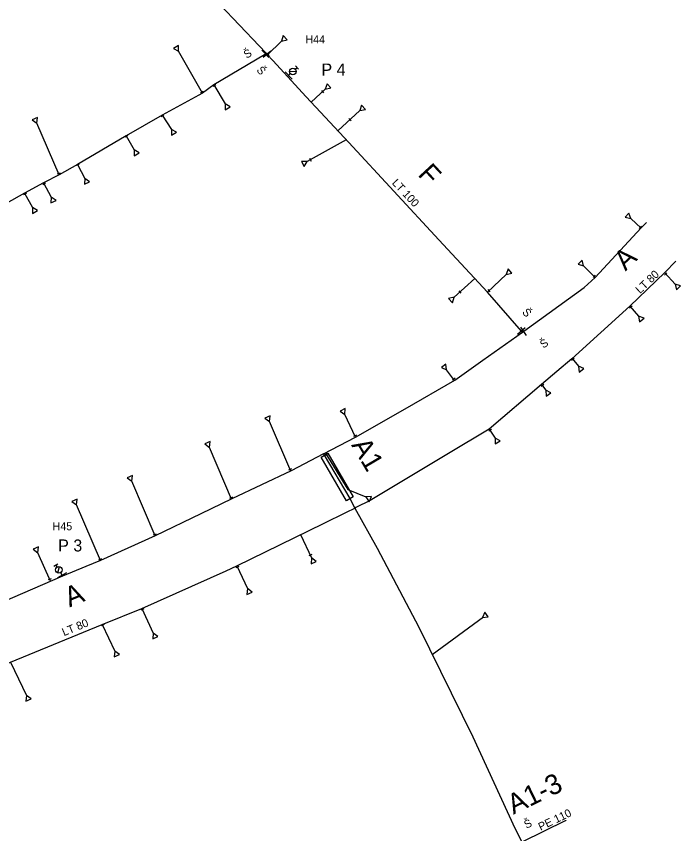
# Model space of a CAD drawing. Extents: x -574467 to -573664, y -1191210 to -1190404.
# Drawn here: x -573951.8 to -573785.7, y -1190810.5 to -1190606.2 of the extents above; entities that cross this region are included whole.
import ezdxf

# ---------------------------------------------------------------- set-up
doc = ezdxf.new("R2010")
doc.units = 0
for name, color, linetype in [('Vrstva 1', 7, 'Continuous'), ('Vrstva 12', 7, 'Continuous'), ('Vrstva 15', 7, 'Continuous'), ('Vrstva 19', 7, 'Continuous'), ('Vrstva 25', 7, 'Continuous'), ('Vrstva 28', 7, 'Continuous'), ('Vrstva 29', 7, 'Continuous'), ('Vrstva 35', 7, 'Continuous'), ('Vrstva 37', 7, 'Continuous')]:
    doc.layers.add(name, color=color, linetype=linetype)

# ---------------------------------------------------------------- blocks, each defined once
blk = doc.blocks.new('160')
at = {"layer": 'Vrstva 1'}
blk.add_circle((0, 0), 0.0458, dxfattribs=at)
blk = doc.blocks.new('147')
at = {"layer": 'Vrstva 1'}
blk.add_line((0, 1.27), (0, -1.27), dxfattribs=at)
blk = doc.blocks.new('133')
at = {"layer": 'Vrstva 1'}
for p, q in [((0.28, 0), (0, 0)), ((0.54, 0.58), (1.7, -0.58)), ((1.94, 0), (2.52, 0)), ((2.52, 0.58), (2.52, -0.58))]:
    blk.add_line(p, q, dxfattribs=at)
blk.add_circle((1.105, 0.003), 0.825, dxfattribs=at)
blk = doc.blocks.new('150')
at = {"layer": 'Vrstva 1'}
blk.add_line((0, 1.27), (0, -1.27), dxfattribs=at)
blk = doc.blocks.new('151')
at = {"layer": 'Vrstva 1'}
blk.add_line((0, 0.4), (0, -0.4), dxfattribs=at)
blk = doc.blocks.new('130')
at = {"layer": 'Vrstva 1'}
for p, q in [((1.25, 0.72), (0, 0)), ((0, 0), (1.25, -0.72)), ((1.25, -0.72), (1.25, 0.72))]:
    blk.add_line(p, q, dxfattribs=at)

msp = doc.modelspace()

# ---------------------------------------------------------------- linework, layer by layer
at = {"layer": 'Vrstva 12'}
for p, q in [((-573889.001, -1190615.839), (-573885.481, -1190612.402)), ((-573905.304, -1190625.432), (-573911.269, -1190614.947)), ((-573902.41, -1190623.348), (-573899.602, -1190628.106)), ((-573878.054, -1190627.677), (-573874.547, -1190624.423)), ((-573871.404, -1190634.844), (-573865.946, -1190629.781)), ((-573915.337, -1190630.924), (-573913.054, -1190634.482)), ((-573941.099, -1190645.798), (-573946.712, -1190632.937)), ((-573924.331, -1190636.089), (-573922.32, -1190639.608)), ((-573869.371, -1190637.036), (-573879.087, -1190642.481)), ((-573936.547, -1190643.211), (-573934.714, -1190646.744)), ((-573945.006, -1190647.851), (-573943.091, -1190651.412)), ((-573949.754, -1190650.437), (-573947.764, -1190654.011)), ((-573795.544, -1190659.125), (-573798.155, -1190656.747)), ((-573807.066, -1190671.468), (-573809.948, -1190668.542)), ((-573834.013, -1190675.152), (-573829.281, -1190670.73)), ((-573789.674, -1190670.297), (-573787.053, -1190673.13)), ((-573837.193, -1190671.724), (-573842.332, -1190676.436)), ((-573798.377, -1190678.633), (-573796.196, -1190681.141)), ((-573812.827, -1190691.761), (-573811.259, -1190693.679)), ((-573842.212, -1190697.206), (-573844.206, -1190694.537)), ((-573820.465, -1190698.209), (-573819.419, -1190699.669)), ((-573866.99, -1190711.399), (-573869.674, -1190705.688)), ((-573883.189, -1190719.88), (-573888.501, -1190707.489)), ((-573833.566, -1190709.355), (-573832.098, -1190711.627)), ((-573898.014, -1190726.854), (-573903.55, -1190713.941)), ((-573917.098, -1190736.064), (-573922.947, -1190722.391)), ((-573930.814, -1190742.242), (-573936.783, -1190728.317)), ((-573880.722, -1190735.76), (-573877.966, -1190741.585)), ((-573943.243, -1190747.418), (-573946.449, -1190740.269)), ((-573896.692, -1190743.581), (-573894.014, -1190749.253)), ((-573920.45, -1190754.23), (-573917.568, -1190760.352)), ((-573847.796, -1190765.753), (-573835.004, -1190756.299)), ((-573930.346, -1190758.182), (-573927.19, -1190764.882)), ((-573953.245, -1190767.614), (-573949.317, -1190775.972))]:
    msp.add_line(p, q, dxfattribs=at)
msp.add_lwpolyline([(-573874.542, -1190715.356), (-573868.887, -1190724.436), (-573864.43, -1190726.32)], dxfattribs=at)
at = {"layer": 'Vrstva 15'}
for p, q in [((-573889.37, -1190615.41), (-573889.54, -1190615.58)), ((-573889.12, -1190615.71), (-573889.37, -1190615.41)), ((-573825.266, -1190685.17), (-573825.51, -1190684.89)), ((-573825.19, -1190812.42), (-573814.47, -1190807.24))]:
    msp.add_line(p, q, dxfattribs=at)
for points in [[(-573889.37, -1190615.41), (-573891.12, -1190613.563), (-573900.955, -1190603.227), (-573909.109, -1190593.884), (-573929.133, -1190571.977), (-573951.697, -1190547.293)], [(-573889.54, -1190615.58), (-573889.752, -1190615.792), (-573902.4, -1190623.34), (-573905.3, -1190625.43), (-573915.33, -1190630.92), (-573924.353, -1190636.102), (-573936.554, -1190643.215), (-573941.075, -1190645.786), (-573944.998, -1190647.847), (-573949.751, -1190650.435), (-573960.986, -1190656.653)], [(-573825.51, -1190684.89), (-573834.023, -1190675.141), (-573846.16, -1190662.057), (-573868.703, -1190637.756), (-573879.333, -1190626.298), (-573887.691, -1190617.287), (-573889.12, -1190615.71)], [(-573786.877, -1190667.404), (-573789.641, -1190670.265), (-573798.387, -1190678.642), (-573812.87, -1190691.8), (-573816.661, -1190695), (-573820.453, -1190698.199), (-573833.612, -1190709.394), (-573843.764, -1190715.49), (-573863.366, -1190727.261), (-573866.886, -1190728.985), (-573867.128, -1190729.122)], [(-573867.128, -1190729.122), (-573868.368, -1190726.761), (-573874.76, -1190715.93), (-573874.965, -1190715.577)], [(-574033.223, -1190787.025), (-574029.297, -1190794.83), (-574026.879, -1190799.637), (-574026.708, -1190799.715), (-574024.277, -1190798.619), (-574015.622, -1190794.716), (-573994.702, -1190785.283), (-573967.518, -1190773.645), (-573957.376, -1190769.359), (-573953.26, -1190767.62), (-573930.346, -1190758.182), (-573920.45, -1190754.23), (-573899.351, -1190744.773), (-573896.692, -1190743.581), (-573874.974, -1190732.946), (-573869.235, -1190730.135), (-573867.128, -1190729.122)], [(-573867.128, -1190729.122), (-573861.589, -1190739.127), (-573851.202, -1190758.85), (-573837.67, -1190786.28), (-573827.129, -1190809.15), (-573825.422, -1190812.532)]]:
    msp.add_lwpolyline(points, dxfattribs=at)
at = {"layer": 'Vrstva 19'}
msp.add_line((-573825.266, -1190685.17), (-573824.942, -1190684.936), dxfattribs=at)
for points in [[(-573824.942, -1190684.936), (-573809.852, -1190674.025), (-573807.074, -1190671.476), (-573795.522, -1190659.102), (-573794.232, -1190657.731)], [(-573874.965, -1190715.577), (-573866.993, -1190711.401), (-573854.582, -1190704.292), (-573842.172, -1190697.183), (-573835.117, -1190692.17), (-573825.266, -1190685.17)], [(-573874.965, -1190715.577), (-573883.096, -1190719.837), (-573897.92, -1190726.808), (-573905.71, -1190730.568), (-573917.081, -1190736.056), (-573930.783, -1190742.229), (-573934.442, -1190743.734), (-573940.284, -1190746.137), (-573974.748, -1190761.051), (-573991.299, -1190768.528), (-574012.217, -1190777.586), (-574028.622, -1190784.688), (-574030.639, -1190785.562)]]:
    msp.add_lwpolyline(points, dxfattribs=at)
at = {"layer": 'Vrstva 25'}
for p, q in [((-573884.022, -1190621.242), (-573883.47, -1190620.73)), ((-573940.284, -1190746.137), (-573940.651, -1190745.496))]:
    msp.add_line(p, q, dxfattribs=at)
at = {"layer": 'Vrstva 37'}
msp.add_lwpolyline([(-573873.896, -1190715.427), (-573867.556, -1190726.317), (-573869.284, -1190727.323), (-573875.624, -1190716.433), (-573873.896, -1190715.427)], dxfattribs=at)

# ---------------------------------------------------------------- block references
at = {"layer": 'Vrstva 12'}
for name, p, xscale, yscale, rotation in [('130', (-573885.481, -1190612.402), 0.9999999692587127, 0.9999999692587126, 43.999999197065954), ('130', (-573911.269, -1190614.947), 0.9999999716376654, 0.9999999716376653, 119.99999896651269), ('151', (-573888.872, -1190615.713), 0.9999999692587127, 0.9999999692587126, 43.999999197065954), ('151', (-573902.286, -1190623.558), 0.9999999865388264, 0.9999999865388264, -59.99999955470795), ('130', (-573874.547, -1190624.423), 0.9999999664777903, 0.9999999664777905, 42.999998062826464), ('151', (-573905.424, -1190625.221), 0.999999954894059, 0.9999999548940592, -60.999999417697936), ('151', (-573875.247, -1190625.073), 0.9999999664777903, 0.9999999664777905, 42.999998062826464), ('130', (-573899.602, -1190628.106), 0.9999999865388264, 0.9999999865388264, -59.99999955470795), ('130', (-573865.946, -1190629.781), 0.9999999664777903, 0.9999999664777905, 42.999998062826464), ('130', (-573946.712, -1190632.937), 0.9999999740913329, 0.9999999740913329, 114.00000060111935), ('151', (-573915.237, -1190631.078), 0.9999999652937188, 0.9999999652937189, -58.00000261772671), ('151', (-573868.357, -1190632.017), 0.9999999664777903, 0.9999999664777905, 42.999998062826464), ('130', (-573913.054, -1190634.482), 0.9999999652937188, 0.9999999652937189, -58.00000261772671), ('151', (-573924.267, -1190636.2), 0.999999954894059, 0.9999999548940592, -60.999999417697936), ('130', (-573922.32, -1190639.608), 0.999999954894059, 0.9999999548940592, -60.999999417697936), ('130', (-573879.087, -1190642.481), 1.0072562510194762, 1.0072562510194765, -151.23333635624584), ('151', (-573878.313, -1190642.047), 1.0037041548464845, 1.0037041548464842, 29.379208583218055), ('151', (-573936.503, -1190643.297), 0.9999999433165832, 0.999999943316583, -64.0000000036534), ('151', (-573941.216, -1190645.529), 0.9999999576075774, 0.9999999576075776, -66.99999911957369), ('130', (-573934.714, -1190646.744), 0.9999999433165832, 0.999999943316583, -64.0000000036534), ('151', (-573944.863, -1190648.117), 0.999999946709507, 0.999999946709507, -62.999999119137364), ('151', (-573949.645, -1190650.633), 0.9999999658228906, 0.9999999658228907, -62.00000017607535), ('130', (-573943.091, -1190651.412), 0.999999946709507, 0.999999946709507, -62.999999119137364), ('130', (-573947.764, -1190654.011), 0.9999999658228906, 0.9999999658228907, -62.00000017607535), ('130', (-573798.155, -1190656.747), 0.9999999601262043, 0.9999999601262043, 138.0000012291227), ('151', (-573795.766, -1190658.923), 0.9999999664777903, 0.9999999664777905, -42.999998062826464), ('130', (-573809.948, -1190668.542), 0.999999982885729, 0.9999999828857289, 135), ('130', (-573829.281, -1190670.73), 0.9999999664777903, 0.9999999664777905, 42.999998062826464), ('151', (-573807.313, -1190671.217), 0.9999999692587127, 0.9999999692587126, -46.00000080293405), ('151', (-573789.4, -1190670.593), 0.9999999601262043, 0.9999999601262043, -48.0000012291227), ('130', (-573787.053, -1190673.13), 0.9999999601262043, 0.9999999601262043, -48.0000012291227), ('151', (-573840.908, -1190675.13), 0.9999999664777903, 0.9999999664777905, 42.999998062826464), ('151', (-573833.652, -1190674.815), 0.9999999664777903, 0.9999999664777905, 42.999998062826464), ('130', (-573842.332, -1190676.436), 0.9999999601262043, 0.9999999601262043, -138.0000012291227), ('151', (-573798.151, -1190678.893), 0.9999999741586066, 0.9999999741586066, -50.000001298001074), ('130', (-573796.196, -1190681.141), 0.9999999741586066, 0.9999999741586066, -50.000001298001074), ('151', (-573812.656, -1190691.97), 0.9999999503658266, 0.9999999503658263, -52.00000018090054), ('130', (-573844.206, -1190694.537), 0.9999999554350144, 0.9999999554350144, 126.99999920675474), ('130', (-573811.259, -1190693.679), 0.9999999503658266, 0.9999999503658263, -52.00000018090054), ('151', (-573842.423, -1190696.922), 0.9999999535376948, 0.9999999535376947, -53.99999865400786), ('151', (-573820.263, -1190698.492), 0.9999999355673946, 0.9999999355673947, -55.0000006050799), ('130', (-573819.419, -1190699.669), 0.9999999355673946, 0.9999999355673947, -55.0000006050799), ('130', (-573869.674, -1190705.688), 0.9999999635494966, 0.9999999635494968, 114.99999960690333), ('130', (-573888.501, -1190707.489), 0.9999999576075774, 0.9999999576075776, 113.00000088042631), ('151', (-573833.329, -1190709.722), 0.9999999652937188, 0.9999999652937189, -58.00000261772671), ('151', (-573867.14, -1190711.082), 0.9999999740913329, 0.9999999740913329, -65.99999939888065), ('130', (-573832.098, -1190711.627), 0.9999999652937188, 0.9999999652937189, -58.00000261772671), ('130', (-573903.55, -1190713.941), 0.9999999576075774, 0.9999999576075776, 113.00000088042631), ('151', (-573874.263, -1190715.804), 0.9999999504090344, 0.9999999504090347, -58.99999841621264), ('151', (-573883.353, -1190719.498), 0.9999999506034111, 0.9999999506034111, -67.99999971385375), ('130', (-573922.947, -1190722.391), 0.9999999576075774, 0.9999999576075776, 113.00000088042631), ('151', (-573898.144, -1190726.551), 0.9999999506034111, 0.9999999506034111, -67.99999971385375), ('130', (-573864.43, -1190726.32), 1.0198568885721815, 1.0198568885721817, -26.39398240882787), ('130', (-573936.783, -1190728.317), 0.9999999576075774, 0.9999999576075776, 113.00000088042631), ('151', (-573917.223, -1190735.773), 0.9999999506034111, 0.9999999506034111, -67.99999971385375), ('130', (-573946.449, -1190740.269), 0.9999999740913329, 0.9999999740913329, 114.00000060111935), ('151', (-573878.294, -1190740.893), 0.9999999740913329, 0.9999999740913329, -65.99999939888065), ('151', (-573930.93, -1190741.971), 0.9999999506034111, 0.9999999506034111, -67.99999971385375), ('130', (-573877.966, -1190741.585), 0.9999999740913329, 0.9999999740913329, -65.99999939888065), ('151', (-573896.545, -1190743.893), 0.9999999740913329, 0.9999999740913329, -65.99999939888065), ('151', (-573943.464, -1190746.925), 0.9999999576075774, 0.9999999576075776, -66.99999911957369), ('130', (-573894.014, -1190749.253), 0.9999999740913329, 0.9999999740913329, -65.99999939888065), ('151', (-573920.341, -1190754.461), 0.9999999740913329, 0.9999999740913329, -65.99999939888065), ('130', (-573835.235, -1190756.47), 0.9999999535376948, 0.9999999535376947, 36.000001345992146), ('151', (-573930.243, -1190758.4), 0.9999999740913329, 0.9999999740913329, -65.99999939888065), ('130', (-573917.568, -1190760.352), 0.9999999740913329, 0.9999999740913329, -65.99999939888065), ('130', (-573927.19, -1190764.882), 0.9999999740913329, 0.9999999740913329, -65.99999939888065), ('130', (-573949.317, -1190775.972), 0.9999999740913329, 0.9999999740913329, -65.99999939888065)]:
    msp.add_blockref(name, p, dxfattribs=dict(at, xscale=xscale, yscale=yscale, rotation=rotation))
at = {"layer": 'Vrstva 25'}
for name, p, xscale, yscale, rotation in [('133', (-573883.47, -1190620.73), 0.9999999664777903, 0.9999999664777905, 42.999998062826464), ('150', (-573883.746, -1190620.986), 0.9999999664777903, 0.9999999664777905, 42.999998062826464), ('133', (-573940.651, -1190745.496), 0.9999999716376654, 0.9999999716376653, 119.99999896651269), ('150', (-573940.411, -1190745.915), 0.999999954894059, 0.9999999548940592, -60.999999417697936)]:
    msp.add_blockref(name, p, dxfattribs=dict(at, xscale=xscale, yscale=yscale, rotation=rotation))
at = {"layer": 'Vrstva 29'}
for name, p, xscale, yscale, rotation in [('147', (-573889.54, -1190615.58), 0.999999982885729, 0.9999999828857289, 45), ('147', (-573889.12, -1190615.71), 0.9999999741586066, 0.9999999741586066, -50.000001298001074), ('160', (-573889.37, -1190615.41), 0.9999999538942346, 0.9999999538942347, -92.0000000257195), ('147', (-573825.51, -1190684.89), 0.9999999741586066, 0.9999999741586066, -50.000001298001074), ('147', (-573824.942, -1190684.936), 0.9999999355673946, 0.9999999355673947, -145.00000060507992), ('160', (-573825.266, -1190685.17), 0.9999999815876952, 0.9999999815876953, -97.99999954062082), ('160', (-573874.965, -1190715.577), 0.9999999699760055, 0.9999999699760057, -106.99999966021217), ('160', (-573867.128, -1190729.122), 1.035124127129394, 1.0351241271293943, -22.503654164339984), ('160', (-573814.47, -1190807.24), 1.0138864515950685, 1.0138864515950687, 27.5653151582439)]:
    msp.add_blockref(name, p, dxfattribs=dict(at, xscale=xscale, yscale=yscale, rotation=rotation))

# ---------------------------------------------------------------- texts
at = {"layer": 'Vrstva 25'}
for s, height, p in [('H44', 2, (-573879.52, -1190612.95)), ('P 4', 3, (-573875.51, -1190621)), ('H45', 2, (-573942.751, -1190734.656)), ('P 3', 3, (-573941.361, -1190739.966))]:
    msp.add_text(s, height=height, dxfattribs=at).set_placement(p)
at = {"layer": 'Vrstva 28'}
for rotation, p in [(30.79, (-573894.234, -1190616.836)), (310.49, (-573891.885, -1190619.71)), (311.63, (-573825.461, -1190680.244)), (35.37, (-573820.003, -1190689.289)), (26.29, (-573824.257, -1190809.301))]:
    msp.add_text('Š', height=2, rotation=rotation, dxfattribs=at).set_placement(p)
at = {"layer": 'Vrstva 35'}
for s, height, rotation, p in [('F', 5, 312.85, (-573851.629, -1190645.868)), ('LT 100', 2, 312.85, (-573858.018, -1190647.946)), ('A', 5, 43.77, (-573799.48, -1190670)), ('LT 80', 2, 43.77, (-573795.836, -1190675.645)), ('A1', 5, 300.55, (-573868.144, -1190713.362)), ('A', 5, 22.39, (-573938.52, -1190753.974)), ('LT 80', 2, 22.39, (-573939.911, -1190761.148)), ('A1-3', 5, 25.79, (-573827.5, -1190805.765)), ('PE 110', 2, 25.79, (-573820.698, -1190809.805))]:
    msp.add_text(s, height=height, rotation=rotation, dxfattribs=at).set_placement(p)

doc.saveas('drawing.dxf')
